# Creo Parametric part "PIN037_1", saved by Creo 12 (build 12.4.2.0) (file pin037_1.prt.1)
Units: Custom; MM, KILOGRAM, SECS

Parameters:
  PTC_WM_ITERATION = "0"
  PTC_WM_VERSION = "-.0"
  PTC_WM_LIFECYCLE_STATE = "In Work"
  PTC_WM_LIFECYCLE = "MO_CADDocument"
  PTC_WM_CREATED_BY = "Maximilian Roepper (Z0017RMS: MO)"
  PTC_WM_CREATED_ON = "18-Sep-26 11:36:42 AM"
  PTC_WM_MODIFIED_BY = "Maximilian Roepper (Z0017RMS: MO)"
  PTC_WM_MODIFIED_ON = "18-Sep-26 11:36:46 AM"
  PDMLINKNUMBER = "PDM000071454826"
  PTC_WM_NAME = "pin037_1.prt"
  PTC_WM_NUMBER = "PDM000071454826"

Other parameters: WEIGHT, WEIGHT_FACTOR, WEIGHT_ADD, _MASS_TEMP, _DIFF_TEMP, MC_ERRORS, SUPPLIER

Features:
  1. coordinate system
  2. datum plane "PRT_YZ"
  3. datum plane "PRT_XY"
  4. datum plane "PRT_XZ"
  5. coordinate system
  6. datum axis
  7. datum axis
  8. datum axis
  9. coordinate system
  10. imported feature

Other named items: PRT, SIEMENS_MO, DRW_VIEW_ORG, PRT_X, PRT_Y, PRT_Z, CS0, ROUGH_GROB

Layers: 00_STD_CSYS-KSYS, 01_STD_PLANES-EBENEN, 02_STD_AXES-ACHSEN, 03_STD_CSYS-KSYS, 24_IMPORT_FEAT-IMPORT_KE

Surfaces: 10 plane, 4 cylinder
